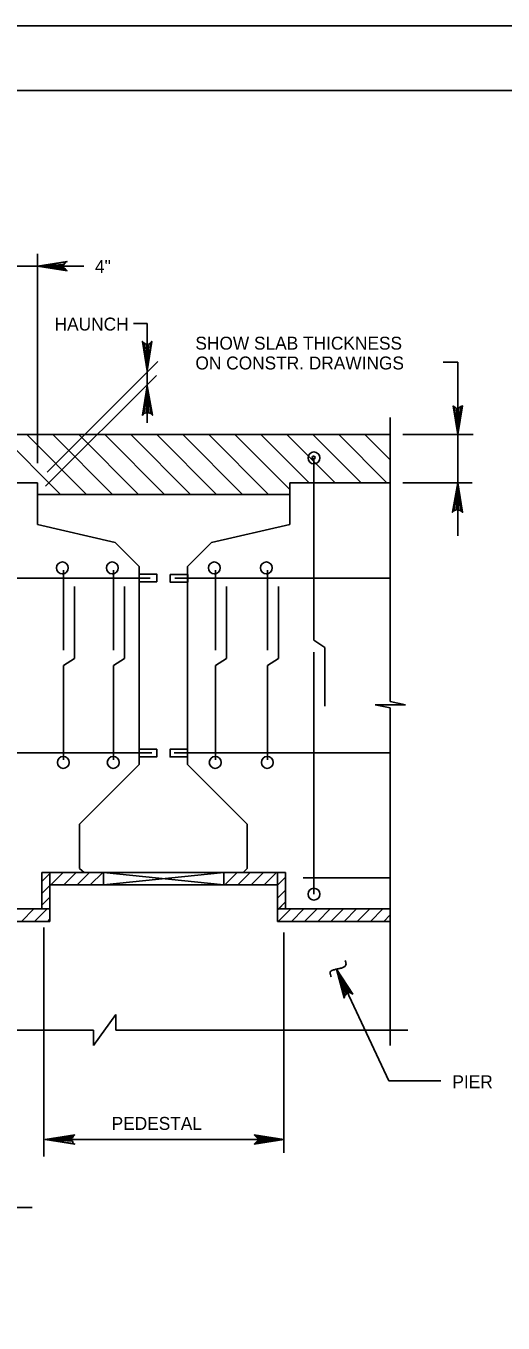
# Model space of a CAD drawing. Extents: x 639980 to 641204, y 298038 to 300414.
# Drawn here: x 640197.5 to 640308.1, y 300113 to 300413.8 of the extents above; entities that cross this region are included whole.
import ezdxf

# ---------------------------------------------------------------- set-up
doc = ezdxf.new("R2010")
doc.units = 0
doc.layers.add('2', color=7, linetype='Continuous')
doc.layers.add('PLT-BNDY', color=7, linetype='Continuous')

msp = doc.modelspace()

# ---------------------------------------------------------------- linework, layer by layer
at = {"layer": '2'}
for p, q in [((640020.31, 300398.78), (640806.31, 300398.78)), ((640200.18, 300312.37), (640200.18, 300360.97)), ((640200.18, 300358.09), (640116.66, 300358.09)), ((640210.91, 300358.09), (640200.18, 300358.09)), ((640222.39, 300344.77), (640225.56, 300344.77)), ((640225.56, 300333.43), (640225.56, 300344.77)), ((640202.42, 300310.29), (640228.08, 300335.95)), ((640297.62, 300335.8), (640294.23, 300335.8)), ((640297.62, 300319.03), (640297.62, 300335.8)), ((640202.06, 300307.04), (640227.72, 300332.71)), ((640225.56, 300321.73), (640225.56, 300333.43)), ((640281.9, 300257.11), (640281.9, 300322.99)), ((640034.94, 300319.03), (640281.9, 300319.03)), ((640191.67, 300319.03), (640205.53, 300305.17)), ((640197.7, 300319.03), (640211.56, 300305.17)), ((640203.73, 300319.03), (640217.59, 300305.17)), ((640209.75, 300319.03), (640223.61, 300305.17)), ((640215.78, 300319.03), (640229.64, 300305.17)), ((640221.81, 300319.03), (640235.67, 300305.17)), ((640227.84, 300319.03), (640241.7, 300305.17)), ((640233.87, 300319.03), (640247.73, 300305.17)), ((640239.89, 300319.03), (640253.75, 300305.17)), ((640245.92, 300319.03), (640258.68, 300306.27)), ((640251.95, 300319.03), (640263.11, 300307.87)), ((640257.98, 300319.03), (640269.14, 300307.87)), ((640264.01, 300319.03), (640275.17, 300307.87)), ((640270.03, 300319.03), (640281.19, 300307.87)), ((640276.06, 300319.03), (640281.9, 300313.19)), ((640301.14, 300319.03), (640284.86, 300319.03)), ((640297.62, 300307.87), (640297.62, 300319.03)), ((640264.26, 300313.63), (640264.26, 300271.33)), ((640200.18, 300307.87), (640116.66, 300307.87)), ((640200.18, 300305.17), (640200.18, 300307.87)), ((640258.68, 300305.17), (640200.18, 300305.17)), ((640200.18, 300298.15), (640200.18, 300305.17)), ((640281.9, 300307.87), (640258.68, 300307.87)), ((640258.68, 300307.87), (640258.68, 300305.17)), ((640258.68, 300305.17), (640258.68, 300305.17)), ((640258.68, 300298.15), (640258.68, 300305.17)), ((640300.97, 300307.87), (640284.86, 300307.87)), ((640297.62, 300295.57), (640297.62, 300307.87)), ((640218.18, 300294.01), (640200.18, 300298.15)), ((640240.5, 300294.01), (640258.68, 300298.15)), ((640223.76, 300288.43), (640218.18, 300294.01)), ((640234.92, 300288.43), (640240.5, 300294.01)), ((640206.18, 300287.6), (640206.18, 300269.08)), ((640217.76, 300287.6), (640217.76, 300269.08)), ((640223.76, 300242.53), (640223.76, 300288.43)), ((640234.92, 300242.53), (640234.92, 300288.43)), ((640241.41, 300287.6), (640241.41, 300269.08)), ((640253.47, 300287.6), (640253.47, 300269.08)), ((640226.28, 300285.73), (640169.94, 300285.73)), ((640281.9, 300285.73), (640232.04, 300285.73)), ((640208.72, 300283.81), (640208.72, 300267.11)), ((640220.3, 300283.81), (640220.3, 300267.11)), ((640243.95, 300283.81), (640243.95, 300267.11)), ((640256.01, 300283.81), (640256.01, 300267.11)), ((640266.78, 300269.7), (640264.26, 300271.33)), ((640266.78, 300269.7), (640266.78, 300256.03)), ((640208.72, 300267.11), (640206.18, 300265.51)), ((640220.3, 300267.11), (640217.76, 300265.51)), ((640243.95, 300267.11), (640241.41, 300265.51)), ((640256.01, 300267.11), (640253.47, 300265.51)), ((640264.26, 300268.59), (640264.26, 300212.47)), ((640206.18, 300265.51), (640206.18, 300243.63)), ((640217.76, 300265.51), (640217.76, 300243.63)), ((640241.41, 300265.51), (640241.41, 300243.63)), ((640253.47, 300265.51), (640253.47, 300243.63)), ((640281.9, 300257.11), (640285.5, 300256.39)), ((640278.48, 300256.39), (640285.5, 300256.39)), ((640278.48, 300256.39), (640281.9, 300255.67)), ((640281.9, 300177.37), (640281.9, 300255.67)), ((640226.64, 300245.23), (640169.58, 300245.23)), ((640281.9, 300245.23), (640231.86, 300245.23)), ((640209.9, 300228.67), (640223.76, 300242.53)), ((640234.92, 300242.53), (640248.78, 300228.67)), ((640209.9, 300218.41), (640209.9, 300228.67)), ((640248.78, 300218.41), (640248.78, 300228.67)), ((640209.9, 300218.41), (640210.98, 300217.51)), ((640248.78, 300218.41), (640247.88, 300217.51)), ((640201.1, 300215.36), (640203, 300217.26)), ((640210.98, 300217.51), (640201.19, 300217.51)), ((640201.19, 300209.05), (640201.19, 300217.51)), ((640203.06, 300206.17), (640203.06, 300217.51)), ((640203.06, 300217.51), (640203.06, 300217.51)), ((640203.24, 300214.63), (640206.12, 300217.51)), ((640206.29, 300214.63), (640209.17, 300217.51)), ((640209.35, 300214.63), (640212.23, 300217.51)), ((640247.88, 300217.51), (640210.98, 300217.51)), ((640212.4, 300214.63), (640215.28, 300217.51)), ((640215.38, 300214.63), (640215.48, 300214.74)), ((640215.48, 300214.63), (640215.48, 300217.51)), ((640215.48, 300217.51), (640243.38, 300214.63)), ((640243.38, 300217.51), (640215.48, 300214.63)), ((640243.38, 300214.63), (640243.38, 300217.51)), ((640243.38, 300217.51), (640243.38, 300217.51)), ((640243.56, 300214.63), (640246.44, 300217.51)), ((640246.61, 300214.63), (640249.49, 300217.51)), ((640257.68, 300217.51), (640247.88, 300217.51)), ((640249.67, 300214.63), (640252.55, 300217.51)), ((640252.72, 300214.63), (640255.6, 300217.51)), ((640255.8, 300206.17), (640255.8, 300217.51)), ((640255.97, 300214.73), (640257.63, 300216.39)), ((640257.68, 300209.05), (640257.68, 300217.51)), ((640281.9, 300216.25), (640261.74, 300216.25)), ((640203, 300214.49), (640201.06, 300212.56)), ((640202.72, 300211.46), (640203.04, 300211.77)), ((640255.8, 300214.63), (640203.06, 300214.63)), ((640215.46, 300214.63), (640215.48, 300214.66)), ((640255.78, 300214.63), (640255.8, 300214.66)), ((640255.82, 300211.57), (640257.71, 300213.47)), ((640203.06, 300209.05), (640113.78, 300209.05)), ((640196.44, 300206.17), (640199.32, 300209.05)), ((640199.49, 300206.17), (640202.37, 300209.05)), ((640201.26, 300209.99), (640202.72, 300211.46)), ((640281.9, 300209.05), (640255.8, 300209.05)), ((640255.8, 300209.05), (640255.8, 300209.05)), ((640257.67, 300210.67), (640255.93, 300208.93)), ((640255.98, 300206.17), (640258.86, 300209.05)), ((640256.13, 300209.13), (640257.67, 300210.67)), ((640259.03, 300206.17), (640261.91, 300209.05)), ((640262.09, 300206.17), (640264.97, 300209.05)), ((640265.14, 300206.17), (640268.02, 300209.05)), ((640268.2, 300206.17), (640271.08, 300209.05)), ((640271.25, 300206.17), (640274.13, 300209.05)), ((640274.31, 300206.17), (640277.19, 300209.05)), ((640277.36, 300206.17), (640280.24, 300209.05)), ((640203.06, 300206.17), (640113.78, 300206.17)), ((640202.55, 300206.17), (640203.06, 300206.69)), ((640202.78, 300206.17), (640203.06, 300206.46)), ((640281.9, 300206.17), (640255.8, 300206.17)), ((640280.42, 300206.17), (640281.9, 300207.66)), ((640201.62, 300151.63), (640201.62, 300204.73)), ((640257.24, 300152.53), (640257.24, 300203.55)), ((640281.59, 300169.19), (640269.46, 300195.07)), ((640213.14, 300177.37), (640218.36, 300184.57)), ((640218.36, 300184.57), (640218.36, 300180.97)), ((640213.14, 300180.97), (640104.6, 300180.97)), ((640213.14, 300180.97), (640213.14, 300177.37)), ((640286.01, 300180.97), (640218.36, 300180.97)), ((640281.59, 300169.19), (640293.65, 300169.19)), ((640257.24, 300155.59), (640201.98, 300155.59)), ((640097.16, 300139.83), (640198.91, 300139.83))]:
    msp.add_line(p, q, dxfattribs=at)
for points in [[(640206.66, 300357.37), (640206.3, 300357.73), (640200.18, 300358.09), (640206.66, 300357.37), (640207.02, 300357.01), (640200.18, 300358.09), (640206.3, 300358.45), (640206.66, 300358.99), (640200.18, 300358.09), (640207.02, 300359.17), (640206.66, 300358.99)], [(640224.84, 300340.27), (640225.38, 300339.91), (640225.56, 300333.79), (640224.84, 300340.27), (640224.48, 300340.63), (640225.56, 300333.79), (640225.92, 300339.91), (640226.46, 300340.27), (640225.56, 300333.79), (640226.64, 300340.63), (640226.46, 300340.27)], [(640226.46, 300323.89), (640225.92, 300324.07), (640225.56, 300330.37), (640226.46, 300323.89), (640226.82, 300323.53), (640225.56, 300330.37), (640225.38, 300324.07), (640224.84, 300323.89), (640225.56, 300330.37), (640224.48, 300323.53), (640224.84, 300323.89)], [(640298.34, 300325.51), (640297.8, 300325.15), (640297.62, 300319.03), (640298.34, 300325.51), (640298.7, 300325.69), (640297.62, 300319.03), (640297.26, 300325.15), (640296.72, 300325.51), (640297.62, 300319.03), (640296.54, 300325.69), (640296.72, 300325.51)], [(640296.72, 300301.39), (640297.26, 300301.57), (640297.62, 300307.87), (640296.72, 300301.39), (640296.36, 300301.03), (640297.62, 300307.87), (640297.8, 300301.57), (640298.34, 300301.39), (640297.62, 300307.87), (640298.7, 300301.03), (640298.34, 300301.39)], [(640271.44, 300188.95), (640271.8, 300189.31), (640269.46, 300195.07), (640271.44, 300188.95), (640271.26, 300188.41), (640269.46, 300195.07), (640272.34, 300189.67), (640272.88, 300189.49), (640269.46, 300195.07), (640273.24, 300189.31), (640272.88, 300189.49)], [(640208.46, 300154.69), (640208.28, 300155.23), (640201.98, 300155.59), (640208.46, 300154.69), (640208.82, 300154.51), (640201.98, 300155.59), (640208.28, 300155.95), (640208.46, 300156.31), (640201.98, 300155.59), (640208.82, 300156.67), (640208.46, 300156.31)], [(640250.76, 300156.31), (640251.12, 300155.95), (640257.24, 300155.59), (640250.76, 300156.31), (640250.4, 300156.67), (640257.24, 300155.59), (640251.12, 300155.23), (640250.76, 300154.87), (640257.24, 300155.59), (640250.4, 300154.51), (640250.76, 300154.87)]]:
    msp.add_lwpolyline(points, dxfattribs=at)
for points in [[(640223.74, 300284.91), (640227.8, 300284.91), (640227.8, 300286.69), (640223.74, 300286.69)], [(640234.99, 300284.8), (640230.93, 300284.8), (640230.93, 300286.58), (640234.99, 300286.58)], [(640223.74, 300244.31), (640227.8, 300244.31), (640227.8, 300246.09), (640223.74, 300246.09)], [(640234.97, 300244.29), (640230.92, 300244.29), (640230.92, 300246.08), (640234.97, 300246.08)]]:
    msp.add_lwpolyline(points, close=True, dxfattribs=at)
for centre, radius in [((640264.26, 300313.63), 1.38), ((640264.19, 300313.7), 0.347), ((640205.93, 300288.11), 1.38), ((640217.51, 300288.11), 1.38), ((640241.16, 300288.11), 1.38), ((640253.22, 300288.11), 1.38), ((640206.15, 300243.02), 1.38), ((640217.73, 300243.02), 1.38), ((640241.38, 300243.02), 1.38), ((640253.44, 300243.02), 1.38), ((640264.26, 300212.47), 1.38)]:
    msp.add_circle(centre, radius, dxfattribs=at)
msp.add_spline([(640271.51, 300197.07), (640271.69, 300196.35), (640271.51, 300195.81), (640270.97, 300195.45), (640270.25, 300195.27), (640269.53, 300195.09), (640268.81, 300194.91), (640268.09, 300194.55), (640268.09, 300193.83), (640268.27, 300193.29)], degree=3, dxfattribs=at)
at = {"layer": 'PLT-BNDY'}
msp.add_lwpolyline([(639980.31, 300413.78), (640821.31, 300413.78), (640821.31, 299819.78), (639980.31, 299819.78)], close=True, dxfattribs=at)

# ---------------------------------------------------------------- texts
at = {"layer": '2'}
for s, height, p in [('4"', 2.999, (640213.5, 300356.52)), ('HAUNCH', 2.999, (640204.13, 300343.16)), ('SHOW SLAB THICKNESS', 2.9987, (640236.77, 300338.73)), ('ON CONSTR. DRAWINGS', 2.9987, (640236.78, 300334.13)), ('PIER', 2.999, (640296.35, 300167.47)), ('PEDESTAL', 2.999, (640217.35, 300157.82))]:
    msp.add_text(s, height=height, dxfattribs=at).set_placement(p)

doc.saveas('drawing.dxf')
